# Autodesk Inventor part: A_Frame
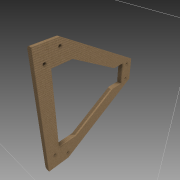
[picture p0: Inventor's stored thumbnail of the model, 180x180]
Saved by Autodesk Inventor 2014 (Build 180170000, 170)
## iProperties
Created: 2013-12
Part Number: A_Frame
Material: MDF Medium Density Fiberboard
Document SubType Name: Modeling
Designer: Bram
Density: 0.8 g/cm^3
Appearance: Cardboard - Corrugated
d0: 7,800 ul
d2: 2,800 ul
d4: 4,625 ul
d6: 28,878 ul
d8: 33,300 ul
d10: 35,400 ul
d12: 37,800 ul
d14: 4,045 ul
d16: 2,900 ul
d18: 4,422 ul
d20: 2,400 ul
d22: 5,350 ul
d24: 13,950 ul
d26: 7,019 ul
d28: 21,250 ul
d30: 8,000 ul
d32: 7,300 ul
d34: 18,000 mm
d35: 0,00 deg
d36: 10,000 mm
Author: Bram
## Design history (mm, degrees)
sketch "Sketch1"
  geometry: L1 (303.237, 40.135)-(5.237, 212.185); L2 (-17.986, 139.185)-(41.677, 139.185); L3 (-17.986, 139.185)-(-28.513, 139.185); L4 (-28.513, 139.185)-(-28.513, -0.315); L5 (-28.513, 212.185)-(5.237, 212.185); L6 (5.237, 212.185)-(-74.763, 212.185); L7 (-74.763, 212.185)-(-74.763, -0.315); L8 (258.237, 39.685)-(214.016, 39.685); L9 (214.016, 39.685)-(41.677, 139.185); L10 (303.237, 40.135)-(303.237, -0.315); L11 (258.237, 39.685)-(258.237, -0.315); L12 (303.237, -40.764)-(5.237, -212.815); L13 (214.016, -40.315)-(41.677, -139.815); L14 (-28.513, -139.815)-(-28.513, -0.315); L15 (-17.986, -139.815)-(41.677, -139.815); L16 (-17.986, -139.815)-(-28.513, -139.815); L17 (-28.513, -212.815)-(5.237, -212.815); L18 (5.237, -212.815)-(-74.763, -212.815); L19 (-74.763, -212.815)-(-74.763, -0.315); L20 (258.237, -40.315)-(214.016, -40.315); L21 (303.237, -40.764)-(303.237, -0.315); L22 (258.237, -40.315)-(258.237, -0.315); L23 (-28.513, 139.185)-(41.677, 139.185); L24 (41.677, 139.185)-(214.016, 39.685); L25 (214.016, 39.685)-(258.237, 39.685); L26 (258.237, 39.685)-(258.237, -40.315); L27 (258.237, -40.315)-(214.016, -40.315); L28 (214.016, -40.315)-(41.677, -139.815); L29 (41.677, -139.815)-(-28.513, -139.815); L30 (-28.513, 139.185)-(-28.513, -139.815); L31 (-74.763, 212.185)-(5.237, 212.185); L32 (5.237, 212.185)-(303.237, 40.135); L33 (303.237, 40.135)-(303.237, -40.764); L34 (303.237, -40.764)-(5.237, -212.815); L35 (5.237, -212.815)-(-74.763, -212.815); L36 (-74.763, -212.815)-(-74.763, 212.185); C1 r 5 at (-46.763, 158.685); C2 r 5 at (3.237, 188.185); C3 r 5 at (279.237, 28.685); C4 r 5 at (-46.763, -159.315); C5 r 5 at (3.237, -188.815); C6 r 5 at (279.237, -29.315)
  constraints: 72 end point, 6 centre point, 6 collinear, 5 perpendicular, 3 parallel
extrude "Extrusion1" new body sketch "Sketch1" distance "d34" = 18; taper "d35" = 0 deg
fillet "Fillet1" dims "d36" = 10
body "Solid1"
other parameters: "d0" = 7.8 (derived), "d2" = 2.8 (derived), "d4" = 4.625 (derived), "d6" = 28.8779 (derived), "d8" = 33.3 (derived), "d10" = 35.4 (derived), "d12" = 37.8 (derived), "d14" = 4.04496 (derived), "d16" = 2.9 (derived), "d18" = 4.42212 (derived), "d20" = 2.4 (derived), "d22" = 5.35 (derived), "d24" = 13.95 (derived), "d26" = 7.01897 (derived), "d28" = 21.25 (derived), "d30" = 8 (derived), "d32" = 7.3 (derived)
